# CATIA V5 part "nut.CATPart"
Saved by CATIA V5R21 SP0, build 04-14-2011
Part number: nut
Bounding box of the stored display mesh (mm): x -17.25 to 17.25, y -19.919 to 19.919, z -10 to 10
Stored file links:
  F:\catia_prac\nut.CATPart
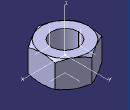
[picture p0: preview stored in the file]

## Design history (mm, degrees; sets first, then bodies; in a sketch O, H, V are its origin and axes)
AxisSystem1: origin (0, 0, 0), X (1, 0, 0), Y (0, 1, 0), Z (0, 0, 1)
Body1 (main body)
  Sketch1 on xy-plane, origin (0, 0, 0), H (1, 0, 0), V (0, 1, 0)
    point P1 (17.25, -9.9593)
    point P2 (17.25, 9.9593)
    point P3 (0, 19.9186)
    point P4 (-17.25, 9.9593)
    point P5 (-17.25, -9.9593)
    point P6 (0, -19.9186)
    point P7 (17.25, 0)
    line L1 (17.25, -9.9593) -> (17.25, 9.9593)
    line L2 (17.25, 9.9593) -> (0, 19.9186)
    line L3 (0, 19.9186) -> (-17.25, 9.9593)
    line L4 (-17.25, 9.9593) -> (-17.25, -9.9593)
    line L5 (-17.25, -9.9593) -> (0, -19.9186)
    line L6 (0, -19.9186) -> (17.25, -9.9593)
    construction line L7 (0, 0) -> (17.25, 0)
    construction circle A1 centre (0, 0) radius 19.9186
    construction arc A2 centre (-17.25, -9.9593) radius 19.9186 from (-17.25, 9.9593) to (0, -19.9186) cw
    construction arc A3 centre (17.25, 9.9593) radius 19.9186 from (0, 19.9186) to (17.25, -9.9593) ccw
    circle A4 centre (0, 0) radius 10
    distance L4 L1 = 34.5
    radius A4 = 10
    horizontal: L7 H
    coincidence: A1 P1, A1 P2, A1 P3, A1 P4, A1 P5, A1 P6, A2 O, A3 O
    midpoint: P7 L1
  Pad1: profile Sketch1, direction (0, 0, 1), length 10
  Sketch2 on yz-plane, origin (0, 0, 0), H (0, 1, 0), V (0, 0, 1)
    point P1 (-17.25, 10)
    line L1 (-17.25, 10) -> (-26.6308, 10)
    line L2 (-26.6308, 10) -> (-26.6308, 4.584)
    line L3 (-26.6308, 4.584) -> (-17.25, 10)
    reference projected line E1 (-9.9593, 10) -> (9.9593, 10) from edge [face of Pad1 from Sketch1.L1 | end face of Pad1]
    reference intersected line E2 through (0, 0) direction (0, 1) from ZX plane of AxisSystem1
    angle L3 L1 = 30
    distance P1 E2 = 17.25
    horizontal: L1 H
    vertical: L2 V
    coincidence: L1 E1
  Groove1: profile Sketch2, axis edge [ZX plane of AxisSystem1 | YZ plane of AxisSystem1], angle 360
  Mirror1: of the body so far, about start face of Pad1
